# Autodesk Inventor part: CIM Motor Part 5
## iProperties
Created: 2010-01
Part Number: CIM Motor Part 5
Document SubType Name: Modeling
Designer: cmcfadden
Density: 1 g/cm^3
Author: cmcfadden
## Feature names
1. Extrusion1
2. Extrusion2
3. Extrusion3
